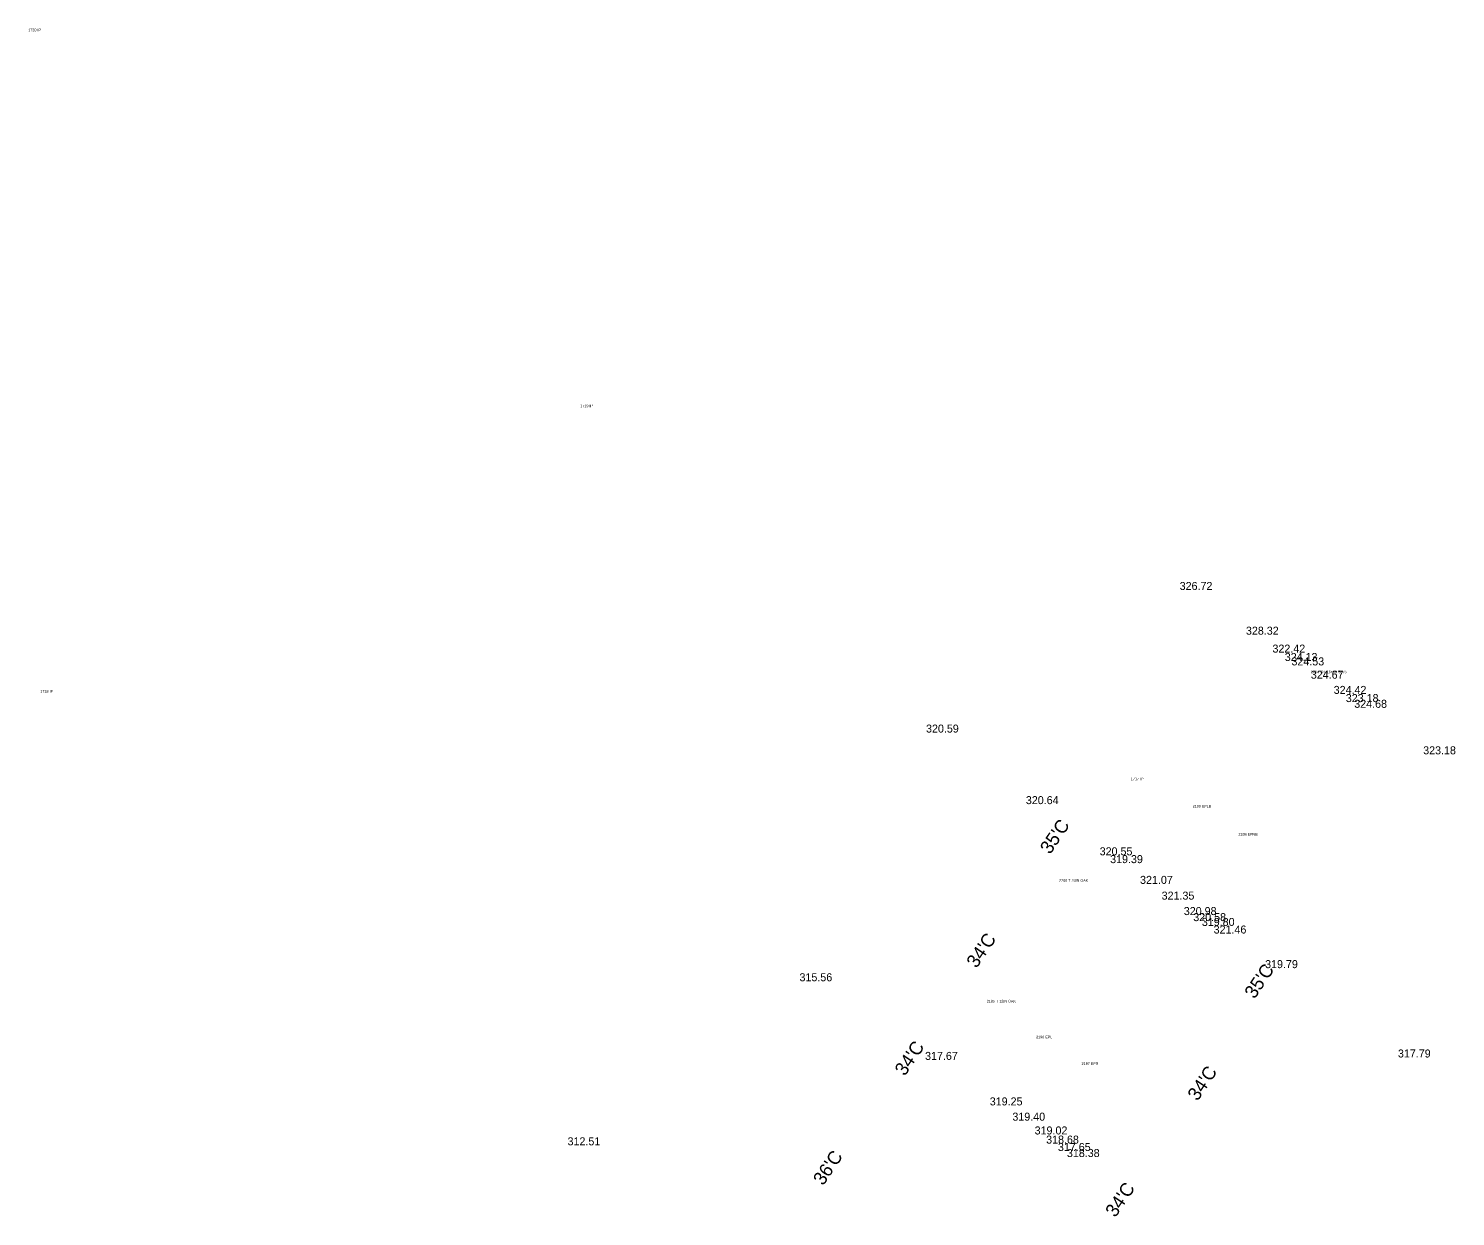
# Model space of a CAD drawing. Extents: x 49683 to 58852, y 49596 to 54801.
# Drawn here: x 56783 to 57318, y 54356 to 54801 of the extents above; entities that cross this region are included whole.
import ezdxf

# ---------------------------------------------------------------- set-up
doc = ezdxf.new("R2010")
doc.units = 0
for name, color, linetype in [('Level 32', 7, 'Continuous'), ('Level 48', 7, 'Continuous'), ('Level 51', 7, 'Continuous'), ('Level 53', 7, 'Continuous'), ('Level 61', 7, 'Continuous'), ('Level 62', 7, 'Continuous')]:
    doc.layers.add(name, color=color, linetype=linetype)

msp = doc.modelspace()

# ---------------------------------------------------------------- texts
at = {"layer": 'Level 32'}
for s, p in [('326.72', (57214.17, 54590.46)), ('328.32', (57239.01, 54573.69)), ('322.42', (57248.95, 54566.98)), ('324.13', (57253.56, 54563.83)), ('324.53', (57256.06, 54562.18)), ('324.67', (57263.32, 54557.2)), ('324.42', (57271.89, 54551.49)), ('323.18', (57276.43, 54548.43)), ('324.68', (57279.6, 54546.29)), ('320.59', (57119.12, 54537)), ('323.18', (57305.43, 54528.85)), ('320.64', (57156.53, 54510.18)), ('320.55', (57184.19, 54491)), ('319.39', (57188.11, 54488.07)), ('321.07', (57199.33, 54480.29)), ('321.35', (57207.41, 54474.39)), ('320.98', (57215.72, 54468.6)), ('320.58', (57219.28, 54466.33)), ('319.80', (57222.48, 54464.53)), ('321.46', (57226.9, 54461.68)), ('319.79', (57246.19, 54448.71)), ('315.56', (57071.7, 54443.79)), ('317.67', (57118.76, 54414.31)), ('317.79', (57295.97, 54415.22)), ('319.25', (57143, 54397.26)), ('319.40', (57151.48, 54391.54)), ('312.51', (56984.78, 54382.3)), ('319.02', (57159.82, 54386.37)), ('318.68', (57164.13, 54382.95)), ('317.65', (57168.55, 54380.17)), ('318.38', (57171.91, 54377.9))]:
    msp.add_text(s, height=3, dxfattribs=at).set_placement(p)
at = {"layer": 'Level 48'}
for s, p in [("35'C", (57165.61, 54491.11)), ("34'C", (57138.05, 54448.44)), ("35'C", (57242.24, 54436.93)), ("34'C", (57111.16, 54408.02)), ("34'C", (57220.89, 54398.65)), ("36'C", (57080.57, 54366.96)), ("34'C", (57190.08, 54355.01))]:
    msp.add_text(s, height=5, rotation=55.9793, dxfattribs=at).set_placement(p)
at = {"layer": 'Level 51'}
msp.add_text('186 POT 16+00 S575 ', height=1, dxfattribs=at).set_placement((57263.35, 54559.26))
at = {"layer": 'Level 53'}
for s, p in [('2199 EPLB ', (57219.04, 54508.9)), ('2198 EPRB ', (57236.17, 54498.33)), ('2196 EPL ', (57160.36, 54422.36)), ('2197 EPR ', (57177.41, 54412.43))]:
    msp.add_text(s, height=1, dxfattribs=at).set_placement(p)
at = {"layer": 'Level 61'}
for s, p in [('2200 T 24IN OAK ', (57168.98, 54481.07)), ('2195 T 12IN OAK ', (57141.88, 54435.83))]:
    msp.add_text(s, height=1, dxfattribs=at).set_placement(p)
at = {"layer": 'Level 62'}
for s, p in [('1720 IP ', (56782.67, 54799.87)), ('1719 IP ', (56989.54, 54658.97)), ('1718 IP ', (56787.18, 54551.96)), ('1717 IP ', (57195.87, 54519.15))]:
    msp.add_text(s, height=1, dxfattribs=at).set_placement(p)

doc.saveas('drawing.dxf')
